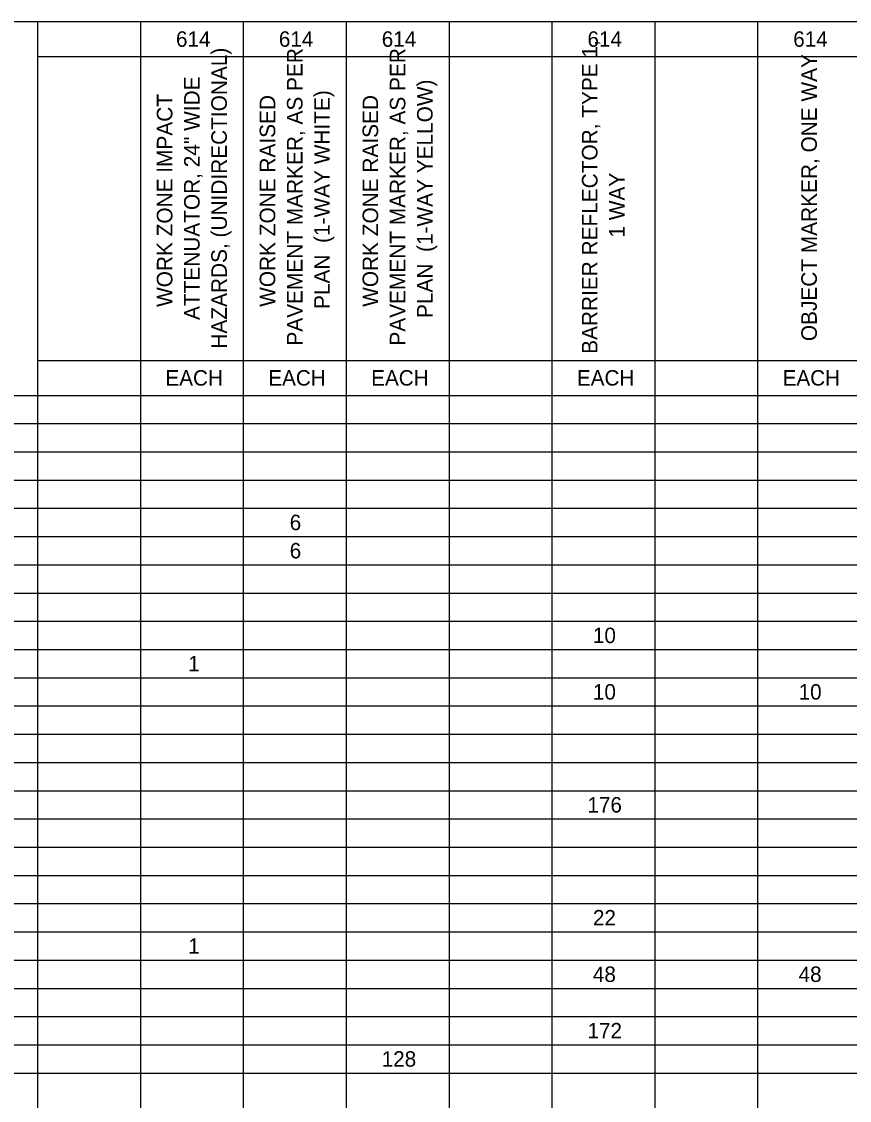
# Model space of a CAD drawing. Extents: x 91011267 to 91022583, y 37007614 to 37014266.
# Drawn here: x 91011643 to 91012046, y 37008139 to 37008664 of the extents above; entities that cross this region are included whole.
import ezdxf

# ---------------------------------------------------------------- set-up
doc = ezdxf.new("R2010")
doc.units = 0
doc.layers.add('SC_Scratch2', color=7, linetype='Continuous')
doc.layers.add('SH_Data', color=7, linetype='Continuous')

msp = doc.modelspace()

# ---------------------------------------------------------------- linework, layer by layer
at = {"layer": 'SC_Scratch2'}
msp.add_lwpolyline([(91011277.35, 37008663.81), (91012802.35, 37008663.81), (91012802.35, 37007613.81), (91011277.35, 37007613.81)], close=True, dxfattribs=at)
at = {"layer": 'SH_Data'}
for p, q in [((91011596.32, 37008663.81), (91011650.36, 37008663.81)), ((91011650.36, 37008663.81), (91011950.88, 37008663.81)), ((91011650.36, 37008663.81), (91011650.36, 37008572.88)), ((91011700.45, 37008663.81), (91011700.45, 37008572.88)), ((91011750.54, 37008663.81), (91011750.54, 37008572.88)), ((91011800.62, 37008663.81), (91011800.62, 37008572.88)), ((91011850.71, 37008663.81), (91011850.71, 37008572.88)), ((91011900.79, 37008663.81), (91011900.79, 37008572.88)), ((91011950.88, 37008663.81), (91012000.97, 37008663.81)), ((91011950.88, 37008663.81), (91011950.88, 37008572.88)), ((91012000.97, 37008663.81), (91012551.92, 37008663.81)), ((91012000.97, 37008663.81), (91012000.97, 37008572.88)), ((91011650.36, 37008646.8), (91011950.88, 37008646.8)), ((91011950.88, 37008646.8), (91012000.97, 37008646.8)), ((91012000.97, 37008646.8), (91012551.92, 37008646.8)), ((91011650.36, 37008572.88), (91011650.36, 37008498.95)), ((91011700.45, 37008572.88), (91011700.45, 37008498.95)), ((91011750.54, 37008572.88), (91011750.54, 37008498.95)), ((91011800.62, 37008572.88), (91011800.62, 37008498.95)), ((91011850.71, 37008572.88), (91011850.71, 37008498.95)), ((91011900.79, 37008572.88), (91011900.79, 37008498.95)), ((91011950.88, 37008572.88), (91011950.88, 37008498.95)), ((91012000.97, 37008572.88), (91012000.97, 37008498.95)), ((91011650.36, 37008498.95), (91011950.88, 37008498.95)), ((91011650.36, 37008498.95), (91011650.36, 37008481.94)), ((91011700.45, 37008498.95), (91011700.45, 37008481.94)), ((91011750.54, 37008498.95), (91011750.54, 37008481.94)), ((91011800.62, 37008498.95), (91011800.62, 37008481.94)), ((91011850.71, 37008498.95), (91011850.71, 37008481.94)), ((91011900.79, 37008498.95), (91011900.79, 37008481.94)), ((91011950.88, 37008498.95), (91012000.97, 37008498.95)), ((91011950.88, 37008498.95), (91011950.88, 37008481.94)), ((91012000.97, 37008498.95), (91012551.92, 37008498.95)), ((91012000.97, 37008498.95), (91012000.97, 37008481.94)), ((91011596.32, 37008481.94), (91011650.36, 37008481.94)), ((91011650.36, 37008481.94), (91011950.88, 37008481.94)), ((91011650.36, 37008481.94), (91011650.36, 37008372.04)), ((91011700.45, 37008481.94), (91011700.45, 37008372.04)), ((91011750.54, 37008481.94), (91011750.54, 37008372.04)), ((91011800.62, 37008481.94), (91011800.62, 37008372.04)), ((91011850.71, 37008481.94), (91011850.71, 37008372.04)), ((91011900.79, 37008481.94), (91011900.79, 37008372.04)), ((91011950.88, 37008481.94), (91012000.97, 37008481.94)), ((91011950.88, 37008481.94), (91011950.88, 37008372.04)), ((91012000.97, 37008481.94), (91012551.92, 37008481.94)), ((91012000.97, 37008481.94), (91012000.97, 37008372.04)), ((91011596.32, 37008468.2), (91011650.36, 37008468.2)), ((91011650.36, 37008468.2), (91011950.88, 37008468.2)), ((91011950.88, 37008468.2), (91012000.97, 37008468.2)), ((91012000.97, 37008468.2), (91012551.92, 37008468.2)), ((91011596.32, 37008454.47), (91011650.36, 37008454.47)), ((91011650.36, 37008454.47), (91011950.88, 37008454.47)), ((91011950.88, 37008454.47), (91012000.97, 37008454.47)), ((91012000.97, 37008454.47), (91012551.92, 37008454.47)), ((91011596.32, 37008440.73), (91011650.36, 37008440.73)), ((91011650.36, 37008440.73), (91011950.88, 37008440.73)), ((91011950.88, 37008440.73), (91012000.97, 37008440.73)), ((91012000.97, 37008440.73), (91012551.92, 37008440.73)), ((91011596.32, 37008426.99), (91011650.36, 37008426.99)), ((91011650.36, 37008426.99), (91011950.88, 37008426.99)), ((91011950.88, 37008426.99), (91012000.97, 37008426.99)), ((91012000.97, 37008426.99), (91012551.92, 37008426.99)), ((91011596.32, 37008413.25), (91011650.36, 37008413.25)), ((91011650.36, 37008413.25), (91011950.88, 37008413.25)), ((91011950.88, 37008413.25), (91012000.97, 37008413.25)), ((91012000.97, 37008413.25), (91012551.92, 37008413.25)), ((91011596.32, 37008399.51), (91011650.36, 37008399.51)), ((91011650.36, 37008399.51), (91011950.88, 37008399.51)), ((91011950.88, 37008399.51), (91012000.97, 37008399.51)), ((91012000.97, 37008399.51), (91012551.92, 37008399.51)), ((91011596.32, 37008385.77), (91011650.36, 37008385.77)), ((91011650.36, 37008385.77), (91011950.88, 37008385.77)), ((91011950.88, 37008385.77), (91012000.97, 37008385.77)), ((91012000.97, 37008385.77), (91012551.92, 37008385.77)), ((91011596.32, 37008372.04), (91011650.36, 37008372.04)), ((91011650.36, 37008372.04), (91011950.88, 37008372.04)), ((91011650.36, 37008372.04), (91011650.36, 37008358.3)), ((91011700.45, 37008372.04), (91011700.45, 37008358.3)), ((91011750.54, 37008372.04), (91011750.54, 37008358.3)), ((91011800.62, 37008372.04), (91011800.62, 37008358.3)), ((91011850.71, 37008372.04), (91011850.71, 37008358.3)), ((91011900.79, 37008372.04), (91011900.79, 37008358.3)), ((91011950.88, 37008372.04), (91012000.97, 37008372.04)), ((91011950.88, 37008372.04), (91011950.88, 37008358.3)), ((91012000.97, 37008372.04), (91012551.92, 37008372.04)), ((91012000.97, 37008372.04), (91012000.97, 37008358.3)), ((91011596.32, 37008358.3), (91011650.36, 37008358.3)), ((91011650.36, 37008358.3), (91011950.88, 37008358.3)), ((91011650.36, 37008358.3), (91011650.36, 37008330.82)), ((91011700.45, 37008358.3), (91011700.45, 37008330.82)), ((91011750.54, 37008358.3), (91011750.54, 37008330.82)), ((91011800.62, 37008358.3), (91011800.62, 37008330.82)), ((91011850.71, 37008358.3), (91011850.71, 37008330.82)), ((91011900.79, 37008358.3), (91011900.79, 37008330.82)), ((91011950.88, 37008358.3), (91012000.97, 37008358.3)), ((91011950.88, 37008358.3), (91011950.88, 37008330.82)), ((91012000.97, 37008358.3), (91012551.92, 37008358.3)), ((91012000.97, 37008358.3), (91012000.97, 37008330.82)), ((91011596.32, 37008344.56), (91011650.36, 37008344.56)), ((91011650.36, 37008344.56), (91011950.88, 37008344.56)), ((91011950.88, 37008344.56), (91012000.97, 37008344.56)), ((91012000.97, 37008344.56), (91012551.92, 37008344.56)), ((91011596.32, 37008330.82), (91011650.36, 37008330.82)), ((91011650.36, 37008330.82), (91011950.88, 37008330.82)), ((91011650.36, 37008330.82), (91011650.36, 37008317.08)), ((91011700.45, 37008330.82), (91011700.45, 37008317.08)), ((91011750.54, 37008330.82), (91011750.54, 37008317.08)), ((91011800.62, 37008330.82), (91011800.62, 37008317.08)), ((91011850.71, 37008330.82), (91011850.71, 37008317.08)), ((91011900.79, 37008330.82), (91011900.79, 37008317.08)), ((91011950.88, 37008330.82), (91012000.97, 37008330.82)), ((91011950.88, 37008330.82), (91011950.88, 37008317.08)), ((91012000.97, 37008330.82), (91012551.92, 37008330.82)), ((91012000.97, 37008330.82), (91012000.97, 37008317.08)), ((91011596.32, 37008317.08), (91011650.36, 37008317.08)), ((91011650.36, 37008317.08), (91011950.88, 37008317.08)), ((91011650.36, 37008317.08), (91011650.36, 37008303.34)), ((91011700.45, 37008317.08), (91011700.45, 37008303.34)), ((91011750.54, 37008317.08), (91011750.54, 37008303.34)), ((91011800.62, 37008317.08), (91011800.62, 37008303.34)), ((91011850.71, 37008317.08), (91011850.71, 37008303.34)), ((91011900.79, 37008317.08), (91011900.79, 37008303.34)), ((91011950.88, 37008317.08), (91012000.97, 37008317.08)), ((91011950.88, 37008317.08), (91011950.88, 37008303.34)), ((91012000.97, 37008317.08), (91012551.92, 37008317.08)), ((91012000.97, 37008317.08), (91012000.97, 37008303.34)), ((91011596.32, 37008303.34), (91011650.36, 37008303.34)), ((91011650.36, 37008303.34), (91011950.88, 37008303.34)), ((91011650.36, 37008303.34), (91011650.36, 37008289.61)), ((91011700.45, 37008303.34), (91011700.45, 37008289.61)), ((91011750.54, 37008303.34), (91011750.54, 37008289.61)), ((91011800.62, 37008303.34), (91011800.62, 37008289.61)), ((91011850.71, 37008303.34), (91011850.71, 37008289.61)), ((91011900.79, 37008303.34), (91011900.79, 37008289.61)), ((91011950.88, 37008303.34), (91012000.97, 37008303.34)), ((91011950.88, 37008303.34), (91011950.88, 37008289.61)), ((91012000.97, 37008303.34), (91012551.92, 37008303.34)), ((91012000.97, 37008303.34), (91012000.97, 37008289.61)), ((91011596.32, 37008289.61), (91011650.36, 37008289.61)), ((91011650.36, 37008289.61), (91011950.88, 37008289.61)), ((91011650.36, 37008289.61), (91011650.36, 37008083.53)), ((91011700.45, 37008289.61), (91011700.45, 37008083.53)), ((91011750.54, 37008289.61), (91011750.54, 37008083.53)), ((91011800.62, 37008289.61), (91011800.62, 37008083.53)), ((91011850.71, 37008289.61), (91011850.71, 37008083.53)), ((91011900.79, 37008289.61), (91011900.79, 37008083.53)), ((91011950.88, 37008289.61), (91012000.97, 37008289.61)), ((91011950.88, 37008289.61), (91011950.88, 37008083.53)), ((91012000.97, 37008289.61), (91012551.92, 37008289.61)), ((91012000.97, 37008289.61), (91012000.97, 37008083.53)), ((91011596.32, 37008275.87), (91011650.36, 37008275.87)), ((91011650.36, 37008275.87), (91011950.88, 37008275.87)), ((91011950.88, 37008275.87), (91012000.97, 37008275.87)), ((91012000.97, 37008275.87), (91012551.92, 37008275.87)), ((91011596.32, 37008262.13), (91011650.36, 37008262.13)), ((91011650.36, 37008262.13), (91011950.88, 37008262.13)), ((91011950.88, 37008262.13), (91012000.97, 37008262.13)), ((91012000.97, 37008262.13), (91012551.92, 37008262.13)), ((91011596.32, 37008248.39), (91011650.36, 37008248.39)), ((91011650.36, 37008248.39), (91011950.88, 37008248.39)), ((91011950.88, 37008248.39), (91012000.97, 37008248.39)), ((91012000.97, 37008248.39), (91012551.92, 37008248.39)), ((91011596.32, 37008234.65), (91011650.36, 37008234.65)), ((91011650.36, 37008234.65), (91011950.88, 37008234.65)), ((91011950.88, 37008234.65), (91012000.97, 37008234.65)), ((91012000.97, 37008234.65), (91012551.92, 37008234.65)), ((91011596.32, 37008220.91), (91011650.36, 37008220.91)), ((91011650.36, 37008220.91), (91011950.88, 37008220.91)), ((91011950.88, 37008220.91), (91012000.97, 37008220.91)), ((91012000.97, 37008220.91), (91012551.92, 37008220.91)), ((91011596.32, 37008207.18), (91011650.36, 37008207.18)), ((91011650.36, 37008207.18), (91011950.88, 37008207.18)), ((91011950.88, 37008207.18), (91012000.97, 37008207.18)), ((91012000.97, 37008207.18), (91012551.92, 37008207.18)), ((91011596.32, 37008193.44), (91011650.36, 37008193.44)), ((91011650.36, 37008193.44), (91011950.88, 37008193.44)), ((91011950.88, 37008193.44), (91012000.97, 37008193.44)), ((91012000.97, 37008193.44), (91012551.92, 37008193.44)), ((91011596.32, 37008179.7), (91011650.36, 37008179.7)), ((91011650.36, 37008179.7), (91011950.88, 37008179.7)), ((91011950.88, 37008179.7), (91012000.97, 37008179.7)), ((91012000.97, 37008179.7), (91012551.92, 37008179.7)), ((91011596.32, 37008165.96), (91011650.36, 37008165.96)), ((91011650.36, 37008165.96), (91011950.88, 37008165.96)), ((91011950.88, 37008165.96), (91012000.97, 37008165.96)), ((91012000.97, 37008165.96), (91012551.92, 37008165.96)), ((91011596.32, 37008152.22), (91011650.36, 37008152.22)), ((91011650.36, 37008152.22), (91011950.88, 37008152.22)), ((91011950.88, 37008152.22), (91012000.97, 37008152.22)), ((91012000.97, 37008152.22), (91012551.92, 37008152.22))]:
    msp.add_line(p, q, dxfattribs=at)

# ---------------------------------------------------------------- texts
for s, height, p in [('614', 7.523, (91011717.78, 37008651.54)), ('614', 7.523, (91011767.86, 37008651.54)), ('614', 7.523, (91011817.95, 37008651.54)), ('614', 7.523, (91011918.12, 37008651.54)), ('614', 7.523, (91012018.3, 37008651.54)), ('EACH', 7.523, (91011712.64, 37008486.69)), ('EACH', 7.523, (91011762.72, 37008486.69)), ('EACH', 7.523, (91011812.81, 37008486.69)), ('EACH', 7.523, (91011912.98, 37008486.69)), ('EACH', 7.523, (91012013.15, 37008486.69)), ('6', 7.52, (91011773.15, 37008416.36)), ('6', 7.52, (91011773.15, 37008402.62)), ('10', 7.523, (91011920.77, 37008361.4)), ('1', 7.52, (91011723.72, 37008347.67)), ('10', 7.523, (91011920.77, 37008333.93)), ('10', 7.523, (91012020.94, 37008333.93)), ('176', 7.523, (91011918.11, 37008278.97)), ('22', 7.523, (91011920.79, 37008224.02)), ('1', 7.52, (91011723.72, 37008210.28)), ('48', 7.523, (91011920.75, 37008196.54)), ('48', 7.523, (91012020.92, 37008196.54)), ('172', 7.523, (91011918.14, 37008169.07)), ('128', 7.523, (91011817.93, 37008155.33))]:
    msp.add_text(s, height=height, dxfattribs=at).set_placement(p)
for s, height, p in [('HAZARDS, (UNIDIRECTIONAL)', 7.5789, (91011742.54, 37008504.71)), ('PAVEMENT MARKER, AS PER ', 7.5789, (91011779.37, 37008506.17)), ('PAVEMENT MARKER, AS PER ', 7.5789, (91011829.45, 37008506.17)), ('BARRIER REFLECTOR, TYPE 1, ', 7.5789, (91011923, 37008502.15)), ('OBJECT MARKER, ONE WAY', 7.5789, (91012029.8, 37008508.34)), ('ATTENUATOR, 24" WIDE ', 7.5789, (91011729.28, 37008518.62)), ('PLAN  (1-WAY YELLOW)', 7.5789, (91011842.72, 37008519.6)), ('PLAN  (1-WAY WHITE)', 7.5789, (91011792.63, 37008523.99)), ('WORK ZONE IMPACT ', 7.5789, (91011716.02, 37008524.97)), ('WORK ZONE RAISED ', 7.5789, (91011766.1, 37008525.03)), ('WORK ZONE RAISED ', 7.5789, (91011816.19, 37008525.03)), ('1 WAY', 7.579, (91011936.26, 37008558.72))]:
    msp.add_text(s, height=height, rotation=90, dxfattribs=at).set_placement(p)

doc.saveas('drawing.dxf')
